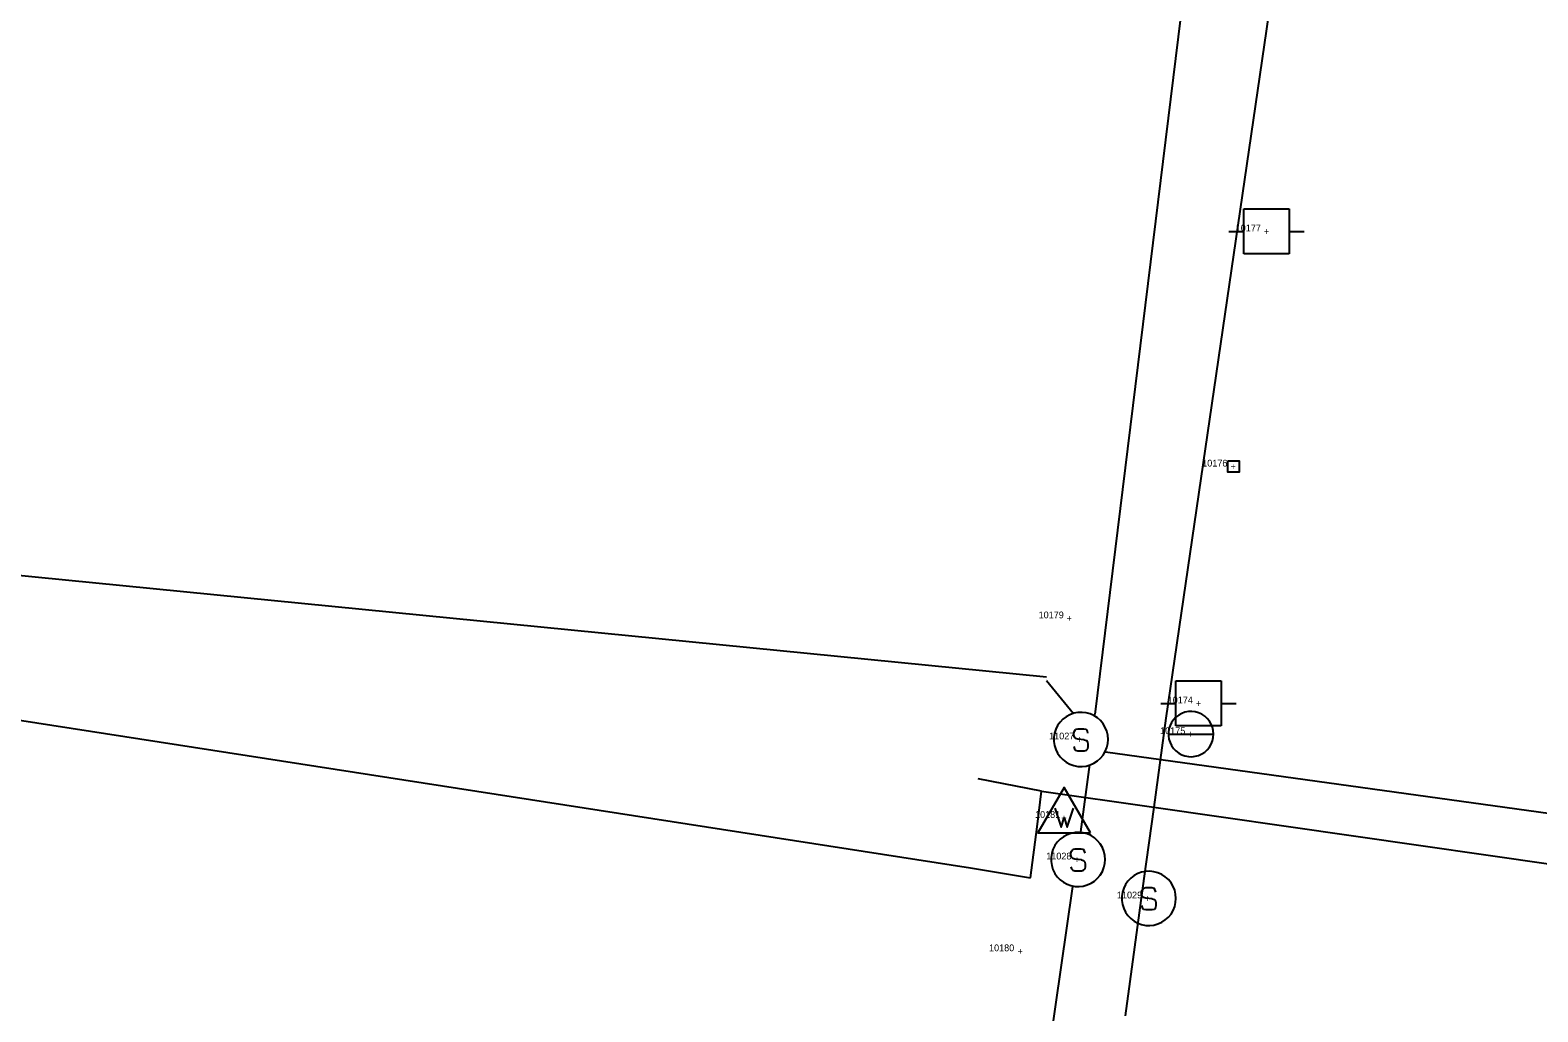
# Model space of a CAD drawing. Extents: x 1795905 to 1799611, y 243768 to 252016.
# Drawn here: x 1797707.1 to 1798040.7, y 247703.5 to 247920.8 of the extents above; entities that cross this region are included whole.
import ezdxf

# ---------------------------------------------------------------- set-up
doc = ezdxf.new("R2010")
doc.units = 0
for name, color, linetype in [('LS-SURVEY POINT', 7, 'Continuous'), ('OHUT', 7, 'Continuous'), ('TOPO', 7, 'Continuous'), ('UGUT', 7, 'Continuous'), ('UGUTTXT', 7, 'Continuous')]:
    doc.layers.add(name, color=color, linetype=linetype)

msp = doc.modelspace()

# ---------------------------------------------------------------- linework, layer by layer
at = {"layer": 'OHUT'}
for p, q in [((1797975.72, 247881.24), (1797985.72, 247881.24)), ((1797975.72, 247871.24), (1797975.72, 247881.24)), ((1797985.72, 247881.24), (1797985.72, 247871.24)), ((1797972.39, 247876.24), (1797975.72, 247876.24)), ((1797985.72, 247876.24), (1797989.05, 247876.24)), ((1797985.72, 247871.24), (1797975.72, 247871.24)), ((1797960.67, 247776.78), (1797970.67, 247776.78)), ((1797960.67, 247766.78), (1797960.67, 247776.78)), ((1797970.67, 247776.78), (1797970.67, 247766.78)), ((1797957.34, 247771.78), (1797960.67, 247771.78)), ((1797970.67, 247771.78), (1797974, 247771.78)), ((1797970.67, 247766.78), (1797960.67, 247766.78))]:
    msp.add_line(p, q, dxfattribs=at)
at = {"layer": 'TOPO'}
msp.add_lwpolyline([(1797972.12, 247825.44), (1797974.62, 247825.44), (1797974.62, 247822.94), (1797972.12, 247822.94)], close=True, dxfattribs=at)
at = {"layer": 'UGUT'}
for p, q in [((1797938.06, 247764.76), (1797938.06, 247765.21)), ((1797938.19, 247764.31), (1797938.06, 247764.76)), ((1797940.81, 247765.97), (1797940.3, 247766.1)), ((1797941.07, 247765.65), (1797940.81, 247765.97)), ((1797941.2, 247765.21), (1797941.07, 247765.65)), ((1797959.32, 247764.98), (1797968.65, 247764.98)), ((1797938.06, 247762.2), (1797938.19, 247761.75)), ((1797938.45, 247763.99), (1797938.19, 247764.31)), ((1797938.19, 247761.75), (1797938.45, 247761.43)), ((1797938.96, 247763.86), (1797938.45, 247763.99)), ((1797938.45, 247761.43), (1797938.96, 247761.3)), ((1797940.36, 247763.73), (1797938.96, 247763.86)), ((1797940.36, 247763.73), (1797940.88, 247763.54)), ((1797940.36, 247761.3), (1797940.88, 247761.43)), ((1797941.2, 247763.22), (1797940.88, 247763.54)), ((1797940.88, 247761.43), (1797941.2, 247761.75)), ((1797941.26, 247762.77), (1797941.2, 247763.22)), ((1797941.2, 247761.75), (1797941.26, 247762.2)), ((1797941.26, 247762.2), (1797941.26, 247762.77)), ((1797938.96, 247761.3), (1797940.36, 247761.3)), ((1797937.43, 247738.19), (1797937.43, 247738.64)), ((1797937.55, 247737.74), (1797937.43, 247738.19)), ((1797940.18, 247739.4), (1797939.67, 247739.53)), ((1797940.43, 247739.08), (1797940.18, 247739.4)), ((1797940.56, 247738.64), (1797940.43, 247739.08)), ((1797937.43, 247735.63), (1797937.55, 247735.18)), ((1797937.81, 247737.42), (1797937.55, 247737.74)), ((1797937.55, 247735.18), (1797937.81, 247734.86)), ((1797938.32, 247737.29), (1797937.81, 247737.42)), ((1797937.81, 247734.86), (1797938.32, 247734.73)), ((1797939.73, 247737.16), (1797938.32, 247737.29)), ((1797938.32, 247734.73), (1797939.73, 247734.73)), ((1797939.73, 247737.16), (1797940.24, 247736.97)), ((1797939.73, 247734.73), (1797940.24, 247734.86)), ((1797940.56, 247736.65), (1797940.24, 247736.97)), ((1797940.24, 247734.86), (1797940.56, 247735.18)), ((1797940.63, 247736.2), (1797940.56, 247736.65)), ((1797940.56, 247735.18), (1797940.63, 247735.63)), ((1797940.63, 247735.63), (1797940.63, 247736.2)), ((1797953.07, 247729.58), (1797953.07, 247730.02)), ((1797953.2, 247729.13), (1797953.07, 247729.58)), ((1797953.45, 247728.81), (1797953.2, 247729.13)), ((1797953.97, 247728.68), (1797953.45, 247728.81)), ((1797955.37, 247728.55), (1797953.97, 247728.68)), ((1797955.82, 247730.79), (1797955.31, 247730.92)), ((1797955.37, 247728.55), (1797955.89, 247728.36)), ((1797956.08, 247730.47), (1797955.82, 247730.79)), ((1797956.21, 247728.04), (1797955.89, 247728.36)), ((1797956.21, 247730.02), (1797956.08, 247730.47)), ((1797956.27, 247727.59), (1797956.21, 247728.04)), ((1797953.07, 247727.02), (1797953.2, 247726.57)), ((1797953.2, 247726.57), (1797953.45, 247726.25)), ((1797953.45, 247726.25), (1797953.97, 247726.12)), ((1797953.97, 247726.12), (1797955.37, 247726.12)), ((1797955.37, 247726.12), (1797955.89, 247726.25)), ((1797955.89, 247726.25), (1797956.21, 247726.57)), ((1797956.21, 247726.57), (1797956.27, 247727.02)), ((1797956.27, 247727.02), (1797956.27, 247727.59))]:
    msp.add_line(p, q, dxfattribs=at)
for points in [[(1797945.65, 247763.8), (1797945.58, 247764.71), (1797945.37, 247765.61), (1797945.03, 247766.46), (1797944.56, 247767.25), (1797943.98, 247767.96), (1797943.29, 247768.57), (1797942.52, 247769.07), (1797941.68, 247769.44), (1797940.79, 247769.69), (1797939.88, 247769.79), (1797938.96, 247769.76), (1797938.06, 247769.58), (1797937.2, 247769.27), (1797936.39, 247768.83), (1797935.66, 247768.28), (1797935.02, 247767.61), (1797934.49, 247766.86), (1797934.09, 247766.04), (1797933.81, 247765.16), (1797933.67, 247764.26), (1797933.67, 247763.34), (1797933.81, 247762.43), (1797934.09, 247761.55), (1797934.49, 247760.73), (1797935.02, 247759.98), (1797935.66, 247759.32), (1797936.39, 247758.76), (1797937.2, 247758.32), (1797938.06, 247758.01), (1797938.96, 247757.84), (1797939.88, 247757.8), (1797940.79, 247757.91), (1797941.68, 247758.15), (1797942.52, 247758.53), (1797943.29, 247759.03), (1797943.98, 247759.64), (1797944.56, 247760.34), (1797945.03, 247761.13), (1797945.37, 247761.99), (1797945.58, 247762.88)], [(1797968.99, 247764.98), (1797968.93, 247765.74), (1797968.75, 247766.49), (1797968.47, 247767.2), (1797968.08, 247767.85), (1797967.59, 247768.44), (1797967.02, 247768.95), (1797966.38, 247769.37), (1797965.68, 247769.68), (1797964.94, 247769.89), (1797964.18, 247769.97), (1797963.41, 247769.94), (1797962.66, 247769.8), (1797961.94, 247769.54), (1797961.27, 247769.17), (1797960.66, 247768.71), (1797960.13, 247768.16), (1797959.69, 247767.53), (1797959.35, 247766.85), (1797959.12, 247766.11), (1797959, 247765.36), (1797959, 247764.59), (1797959.12, 247763.84), (1797959.35, 247763.11), (1797959.69, 247762.42), (1797960.13, 247761.8), (1797960.66, 247761.24), (1797961.27, 247760.78), (1797961.94, 247760.41), (1797962.66, 247760.15), (1797963.41, 247760.01), (1797964.18, 247759.98), (1797964.94, 247760.07), (1797965.68, 247760.27), (1797966.38, 247760.58), (1797967.02, 247761), (1797967.59, 247761.51), (1797968.08, 247762.1), (1797968.47, 247762.76), (1797968.75, 247763.47), (1797968.93, 247764.21)], [(1797941.76, 247743.13), (1797935.93, 247753.13), (1797930.1, 247743.13)], [(1797945.02, 247737.23), (1797944.95, 247738.14), (1797944.74, 247739.04), (1797944.39, 247739.89), (1797943.93, 247740.68), (1797943.34, 247741.39), (1797942.66, 247742), (1797941.88, 247742.5), (1797941.05, 247742.87), (1797940.16, 247743.12), (1797939.25, 247743.22), (1797938.33, 247743.19), (1797937.43, 247743.01), (1797936.56, 247742.7), (1797935.76, 247742.26), (1797935.03, 247741.71), (1797934.39, 247741.04), (1797933.86, 247740.29), (1797933.45, 247739.47), (1797933.18, 247738.59), (1797933.04, 247737.69), (1797933.04, 247736.77), (1797933.18, 247735.86), (1797933.45, 247734.98), (1797933.86, 247734.16), (1797934.39, 247733.41), (1797935.03, 247732.75), (1797935.76, 247732.19), (1797936.56, 247731.75), (1797937.43, 247731.44), (1797938.33, 247731.27), (1797939.25, 247731.23), (1797940.16, 247731.34), (1797941.05, 247731.58), (1797941.88, 247731.96), (1797942.66, 247732.46), (1797943.34, 247733.07), (1797943.93, 247733.77), (1797944.39, 247734.56), (1797944.74, 247735.42), (1797944.95, 247736.31)], [(1797960.66, 247728.61), (1797960.59, 247729.53), (1797960.38, 247730.42), (1797960.04, 247731.28), (1797959.57, 247732.07), (1797958.98, 247732.77), (1797958.3, 247733.39), (1797957.53, 247733.88), (1797956.69, 247734.26), (1797955.8, 247734.5), (1797954.89, 247734.61), (1797953.97, 247734.57), (1797953.07, 247734.4), (1797952.21, 247734.09), (1797951.4, 247733.65), (1797950.67, 247733.09), (1797950.03, 247732.43), (1797949.5, 247731.68), (1797949.1, 247730.86), (1797948.82, 247729.98), (1797948.68, 247729.07), (1797948.68, 247728.15), (1797948.82, 247727.25), (1797949.1, 247726.37), (1797949.5, 247725.55), (1797950.03, 247724.8), (1797950.67, 247724.13), (1797951.4, 247723.58), (1797952.21, 247723.14), (1797953.07, 247722.83), (1797953.97, 247722.65), (1797954.89, 247722.62), (1797955.8, 247722.72), (1797956.69, 247722.97), (1797957.53, 247723.34), (1797958.3, 247723.84), (1797958.98, 247724.45), (1797959.57, 247725.16), (1797960.04, 247725.95), (1797960.38, 247726.8), (1797960.59, 247727.7)]]:
    msp.add_lwpolyline(points, close=True, dxfattribs=at)
for points in [[(1797938.06, 247765.21), (1797938.19, 247765.65), (1797938.45, 247765.97)], [(1797940.3, 247766.1), (1797938.96, 247766.1), (1797938.45, 247765.97)], [(1797933.85, 247748.55), (1797935.24, 247744.38), (1797935.93, 247746.46), (1797936.62, 247744.38), (1797938.01, 247748.55)], [(1797937.43, 247738.64), (1797937.55, 247739.08), (1797937.81, 247739.4)], [(1797939.67, 247739.53), (1797938.32, 247739.53), (1797937.81, 247739.4)], [(1797953.07, 247730.02), (1797953.2, 247730.47), (1797953.45, 247730.79)], [(1797955.31, 247730.92), (1797953.97, 247730.92), (1797953.45, 247730.79)]]:
    msp.add_lwpolyline(points, dxfattribs=at)
at = {"layer": 'UGUTTXT'}
for p, q in [((1797942.79, 247769.31), (1797985.87, 248119.72)), ((1797932.01, 247776.85), (1797937.97, 247769.56)), ((1797932.06, 247776.98), (1797932.06, 247776.98)), ((1797939.6, 247743.34), (1797941.6, 247758.21)), ((1797945.05, 247761.08), (1798133.16, 247734.98)), ((1797831.67, 246994.25), (1797937.87, 247731.28))]:
    msp.add_line(p, q, dxfattribs=at)
for points in [[(1798010.15, 248122.69), (1797958.43, 247768.51)], [(1797931.99, 247777.57), (1797589.55, 247811.4), (1797402.95, 247837.78)], [(1797595.02, 247785.07), (1797915.19, 247735.41)], [(1797958.43, 247768.51), (1797955.74, 247748.81)], [(1797930.93, 247752.37), (1797916.89, 247755.05)], [(1797929.92, 247744.43), (1797930.93, 247752.37)], [(1797930.93, 247752.37), (1797955.74, 247748.81)], [(1797955.74, 247748.81), (1797953.58, 247732.99)], [(1797955.74, 247748.81), (1798265.02, 247704.41)], [(1797928.49, 247733.15), (1797929.92, 247744.43)], [(1797915.19, 247735.41), (1797928.49, 247733.15)], [(1797953.58, 247732.99), (1797949.42, 247702.6)]]:
    msp.add_lwpolyline(points, dxfattribs=at)

# ---------------------------------------------------------------- texts
at = {"layer": 'LS-SURVEY POINT'}
for s, p in [('10177', (1797973.89, 247876.24)), ('+', (1797980.09, 247875.49)), ('10176', (1797966.47, 247824.19)), ('+', (1797972.74, 247823.44)), ('10179', (1797930.27, 247790.6)), ('+', (1797936.47, 247789.85)), ('10174', (1797958.84, 247771.78)), ('+', (1797965.04, 247771.03)), ('11027', (1797932.6, 247763.8)), ('10175', (1797957.16, 247764.98)), ('+', (1797963.36, 247764.23)), ('+', (1797938.8, 247763.05)), ('10181', (1797929.48, 247746.43)), ('+', (1797935.3, 247745.68)), ('11028', (1797931.96, 247737.23)), ('+', (1797938.16, 247736.48)), ('11029', (1797947.6, 247728.61)), ('+', (1797953.81, 247727.86)), ('10180', (1797919.3, 247716.92)), ('+', (1797925.61, 247716.17))]:
    msp.add_text(s, height=1.5, dxfattribs=at).set_placement(p)
at = {"layer": 'TOPO'}
msp.add_text('+', height=0.1, dxfattribs=at).set_placement((1797973.32, 247824.14))

doc.saveas('drawing.dxf')
